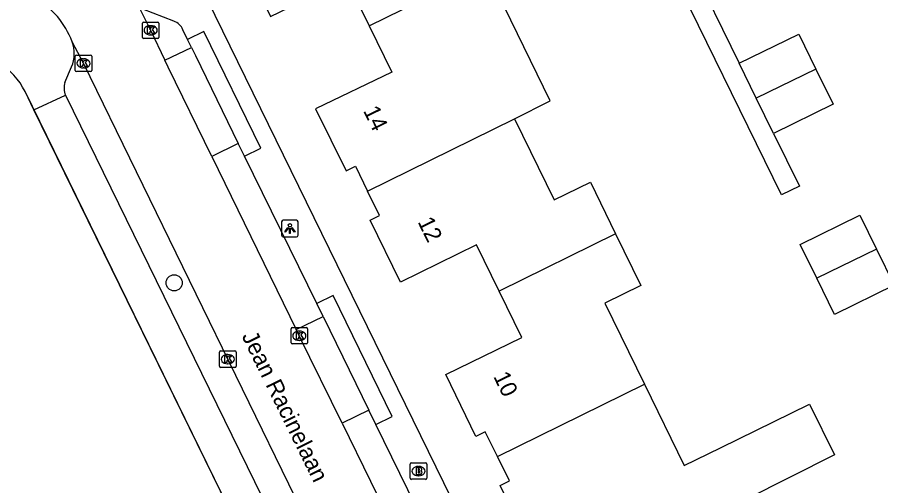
# Model space of a CAD drawing. Extents: x 160457 to 162082, y 388340 to 389736.
# Drawn here: x 160698.2 to 160750.4, y 388899 to 388927.4 of the extents above; entities that cross this region are included whole.
import ezdxf

# ---------------------------------------------------------------- set-up
doc = ezdxf.new("R2010")
doc.units = 0
for name, color, linetype in [('IMGEO_Boom', 7, 'Continuous'), ('IMGEO_Brandkraan', 7, 'Continuous'), ('IMGEO_Kolk', 7, 'Continuous'), ('IMGEO_Lichtpunt', 7, 'Continuous'), ('IMGEO_Muur', 7, 'Continuous'), ('IMGEO_Openbare_ruimte_label', 7, 'Continuous'), ('IMGEO_Pand', 7, 'Continuous'), ('IMGEO_Pand_nummerreeks', 7, 'Continuous'), ('IMGEO_Parkeervlak_open', 7, 'Continuous'), ('IMGEO_Rijbaan_lokaal_gesloten', 7, 'Continuous'), ('IMGEO_Rijbaan_lokaal_open', 7, 'Continuous'), ('IMGEO_Voetpad_open', 7, 'Continuous')]:
    doc.layers.add(name, color=color, linetype=linetype)

msp = doc.modelspace()

# ---------------------------------------------------------------- linework, layer by layer
at = {"layer": 'IMGEO_Boom'}
msp.add_circle((160707.652, 388911.311), 0.489, dxfattribs=at)
at = {"layer": 'IMGEO_Brandkraan'}
for p, q in [((160721.93, 388899.495), (160721.93, 388900.347)), ((160722.005, 388900.421), (160722.857, 388900.421)), ((160722.931, 388900.347), (160722.931, 388899.495)), ((160722.418, 388900.201), (160722.443, 388900.201)), ((160722.857, 388899.421), (160722.005, 388899.421)), ((160722.441, 388899.641), (160722.416, 388899.641))]:
    msp.add_line(p, q, dxfattribs=at)
for points in [[(160721.93, 388899.495), (160721.93, 388900.347)], [(160722.005, 388900.421), (160722.857, 388900.421)], [(160722.931, 388900.347), (160722.931, 388899.495)], [(160722.278, 388900.121), (160722.278, 388899.721), (160722.491, 388899.721)], [(160722.509, 388900.121), (160722.278, 388900.121)], [(160722.457, 388900.04), (160722.403, 388900.04), (160722.403, 388899.964)], [(160722.403, 388899.964), (160722.456, 388899.964)], [(160722.465, 388899.888), (160722.403, 388899.888), (160722.403, 388899.807)], [(160722.403, 388899.807), (160722.465, 388899.807)], [(160722.857, 388899.421), (160722.005, 388899.421)]]:
    msp.add_lwpolyline(points, dxfattribs=at)
for centre, radius, start, end in [((160722.007, 388900.345), 0.0765, 91.552, 178.448), ((160722.007, 388900.345), 0.0765, 91.552, 178.448), ((160722.855, 388900.345), 0.0765, 1.552, 88.448), ((160722.855, 388900.345), 0.0765, 1.552, 88.448), ((160722.458, 388900.002), 0.0379, 267.8285, 90.9355), ((160722.466, 388899.847), 0.0404, 269.8759, 90.5077), ((160722.497, 388899.972), 0.251, 268.6676, 293.5347), ((160722.513, 388899.976), 0.145, 59.4692, 91.5367), ((160722.538, 388900.023), 0.0922, 285.5137, 58.1501), ((160722.543, 388899.831), 0.105, 301.3115, 78.989), ((160722.007, 388899.497), 0.0765, 181.552, 268.448), ((160722.007, 388899.497), 0.0765, 181.552, 268.448), ((160722.855, 388899.497), 0.0765, 271.552, 358.448), ((160722.855, 388899.497), 0.0765, 271.552, 358.448)]:
    msp.add_arc(centre, radius, start, end, dxfattribs=at)
for centre, major_axis, ratio, start_param, end_param in [((160722.417, 388899.921), (-0.387, 0.002), 0.722429, 4.712389, 7.853982), ((160722.442, 388899.921), (-0.39, 0.002), 0.717154, 1.570796, 4.712389)]:
    msp.add_ellipse(centre, major_axis=major_axis, ratio=ratio, start_param=start_param, end_param=end_param, dxfattribs=at)
at = {"layer": 'IMGEO_Kolk'}
for p, q in [((160705.728, 388926.167), (160705.728, 388927.019)), ((160705.803, 388927.093), (160706.655, 388927.093)), ((160706.216, 388926.873), (160706.241, 388926.873)), ((160706.729, 388927.019), (160706.729, 388926.167)), ((160706.655, 388926.093), (160705.803, 388926.093)), ((160706.239, 388926.313), (160706.214, 388926.313)), ((160701.669, 388924.168), (160701.669, 388925.02)), ((160701.744, 388925.094), (160702.596, 388925.094)), ((160702.157, 388924.874), (160702.182, 388924.874)), ((160702.67, 388925.02), (160702.67, 388924.168)), ((160702.18, 388924.314), (160702.155, 388924.314)), ((160702.596, 388924.094), (160701.744, 388924.094)), ((160714.795, 388908.611), (160715.647, 388908.611)), ((160714.72, 388907.685), (160714.72, 388908.537)), ((160715.208, 388908.391), (160715.233, 388908.391)), ((160715.721, 388908.537), (160715.721, 388907.685)), ((160715.647, 388907.611), (160714.795, 388907.611)), ((160715.231, 388907.831), (160715.206, 388907.831)), ((160710.393, 388906.269), (160710.393, 388907.121)), ((160710.468, 388907.195), (160711.32, 388907.195)), ((160711.394, 388907.121), (160711.394, 388906.269)), ((160710.881, 388906.975), (160710.906, 388906.975)), ((160711.32, 388906.195), (160710.468, 388906.195)), ((160710.904, 388906.415), (160710.879, 388906.415))]:
    msp.add_line(p, q, dxfattribs=at)
for points in [[(160705.728, 388926.167), (160705.728, 388927.019)], [(160705.803, 388927.093), (160706.655, 388927.093)], [(160706.729, 388927.019), (160706.729, 388926.167)], [(160706.049, 388926.793), (160706.172, 388926.793), (160706.172, 388926.642), (160706.302, 388926.793), (160706.466, 388926.793), (160706.32, 388926.642), (160706.473, 388926.393), (160706.321, 388926.393), (160706.236, 388926.557), (160706.172, 388926.49), (160706.172, 388926.393), (160706.049, 388926.393), (160706.049, 388926.793)], [(160706.655, 388926.093), (160705.803, 388926.093)], [(160701.669, 388924.168), (160701.669, 388925.02)], [(160701.744, 388925.094), (160702.596, 388925.094)], [(160701.99, 388924.794), (160702.113, 388924.794), (160702.113, 388924.643), (160702.243, 388924.794), (160702.407, 388924.794), (160702.261, 388924.643), (160702.414, 388924.394), (160702.262, 388924.394), (160702.177, 388924.558), (160702.113, 388924.491), (160702.113, 388924.394), (160701.99, 388924.394), (160701.99, 388924.794)], [(160702.67, 388925.02), (160702.67, 388924.168)], [(160702.596, 388924.094), (160701.744, 388924.094)], [(160714.795, 388908.611), (160715.647, 388908.611)], [(160714.72, 388907.685), (160714.72, 388908.537)], [(160715.041, 388908.311), (160715.164, 388908.311), (160715.164, 388908.16), (160715.294, 388908.311), (160715.458, 388908.311), (160715.312, 388908.16), (160715.465, 388907.911), (160715.313, 388907.911), (160715.228, 388908.075), (160715.164, 388908.008), (160715.164, 388907.911), (160715.041, 388907.911), (160715.041, 388908.311)], [(160715.721, 388908.537), (160715.721, 388907.685)], [(160715.647, 388907.611), (160714.795, 388907.611)], [(160710.393, 388906.269), (160710.393, 388907.121)], [(160710.468, 388907.195), (160711.32, 388907.195)], [(160711.394, 388907.121), (160711.394, 388906.269)], [(160710.714, 388906.895), (160710.837, 388906.895), (160710.837, 388906.744), (160710.967, 388906.895), (160711.131, 388906.895), (160710.985, 388906.744), (160711.138, 388906.495), (160710.986, 388906.495), (160710.901, 388906.659), (160710.837, 388906.592), (160710.837, 388906.495), (160710.714, 388906.495), (160710.714, 388906.895)], [(160711.32, 388906.195), (160710.468, 388906.195)]]:
    msp.add_lwpolyline(points, dxfattribs=at)
for centre, start, end in [((160705.805, 388927.017), 91.552, 178.448), ((160705.805, 388927.017), 91.552, 178.448), ((160706.653, 388927.017), 1.552, 88.448), ((160706.653, 388927.017), 1.552, 88.448), ((160705.805, 388926.169), 181.552, 268.448), ((160705.805, 388926.169), 181.552, 268.448), ((160706.653, 388926.169), 271.552, 358.448), ((160706.653, 388926.169), 271.552, 358.448), ((160701.746, 388925.018), 91.552, 178.448), ((160701.746, 388925.018), 91.552, 178.448), ((160702.594, 388925.018), 1.552, 88.448), ((160702.594, 388925.018), 1.552, 88.448), ((160701.746, 388924.17), 181.552, 268.448), ((160701.746, 388924.17), 181.552, 268.448), ((160702.594, 388924.17), 271.552, 358.448), ((160702.594, 388924.17), 271.552, 358.448), ((160714.797, 388908.535), 91.552, 178.448), ((160714.797, 388908.535), 91.552, 178.448), ((160715.645, 388908.535), 1.552, 88.448), ((160715.645, 388908.535), 1.552, 88.448), ((160714.797, 388907.687), 181.552, 268.448), ((160714.797, 388907.687), 181.552, 268.448), ((160715.645, 388907.687), 271.552, 358.448), ((160715.645, 388907.687), 271.552, 358.448), ((160710.47, 388907.119), 91.552, 178.448), ((160710.47, 388907.119), 91.552, 178.448), ((160711.318, 388907.119), 1.552, 88.448), ((160711.318, 388907.119), 1.552, 88.448), ((160710.47, 388906.271), 181.552, 268.448), ((160710.47, 388906.271), 181.552, 268.448), ((160711.318, 388906.271), 271.552, 358.448), ((160711.318, 388906.271), 271.552, 358.448)]:
    msp.add_arc(centre, 0.0765, start, end, dxfattribs=at)
for centre, major_axis, ratio, start_param, end_param in [((160706.215, 388926.593), (-0.387, 0.002), 0.722429, 4.712389, 7.853982), ((160706.24, 388926.593), (-0.39, 0.002), 0.717154, 1.570796, 4.712389), ((160702.156, 388924.594), (-0.387, 0.002), 0.722429, 4.712389, 7.853982), ((160702.181, 388924.594), (-0.39, 0.002), 0.717154, 1.570796, 4.712389), ((160715.207, 388908.111), (-0.387, 0.002), 0.722429, 4.712389, 7.853982), ((160715.232, 388908.111), (-0.39, 0.002), 0.717154, 1.570796, 4.712389), ((160710.88, 388906.695), (-0.387, 0.002), 0.722429, 4.712389, 7.853982), ((160710.905, 388906.695), (-0.39, 0.002), 0.717154, 1.570796, 4.712389)]:
    msp.add_ellipse(centre, major_axis=major_axis, ratio=ratio, start_param=start_param, end_param=end_param, dxfattribs=at)
at = {"layer": 'IMGEO_Lichtpunt'}
for p, q in [((160714.15, 388914.999), (160714.15, 388914.192)), ((160714.15, 388914.999), (160714.15, 388914.192)), ((160715.052, 388915.094), (160714.244, 388915.094)), ((160715.052, 388915.094), (160714.244, 388915.094)), ((160715.146, 388914.192), (160715.146, 388914.999)), ((160715.146, 388914.192), (160715.146, 388914.999)), ((160714.244, 388914.098), (160715.052, 388914.098)), ((160714.244, 388914.098), (160715.052, 388914.098))]:
    msp.add_line(p, q, dxfattribs=at)
for points in [[(160714.524, 388914.663), (160714.563, 388914.635), (160714.375, 388914.373), (160714.337, 388914.4), (160714.524, 388914.663)], [(160714.626, 388914.615), (160714.673, 388914.615), (160714.673, 388914.293), (160714.626, 388914.293), (160714.626, 388914.615)], [(160714.736, 388914.635), (160714.774, 388914.662), (160714.961, 388914.4), (160714.922, 388914.372), (160714.736, 388914.635)]]:
    msp.add_lwpolyline(points, dxfattribs=at)
msp.add_circle((160714.649, 388914.797), 0.0994, dxfattribs=at)
for centre, start, end in [((160714.244, 388914.999), 90, 180), ((160714.244, 388914.999), 90, 180), ((160715.052, 388914.999), 0, 90), ((160715.052, 388914.999), 0, 90), ((160714.244, 388914.192), 180, 270), ((160714.244, 388914.192), 180, 270), ((160715.052, 388914.192), 270, 0), ((160715.052, 388914.192), 270, 360)]:
    msp.add_arc(centre, 0.0946, start, end, dxfattribs=at)
at = {"layer": 'IMGEO_Muur'}
msp.add_lwpolyline([(160711.402, 388896.761), (160698.632, 388922.881)], dxfattribs=at)
msp.add_arc((160694.823, 388921.023), 4.238, 26.0033, 154.6119, dxfattribs=at)
at = {"layer": 'IMGEO_Pand'}
for points in [[(160711.473, 388932.933), (160712.196, 388931.461), (160711.631, 388931.184), (160713.469, 388927.434), (160718.071, 388929.671), (160719.442, 388926.87)], [(160719.442, 388926.87), (160726.489, 388930.328)], [(160728.231, 388921.239), (160730.401, 388922.33), (160728.012, 388927.214), (160726.489, 388930.328)], [(160719.442, 388926.87), (160720.813, 388924.069), (160716.205, 388921.838), (160718.045, 388918.085), (160718.61, 388918.362), (160719.343, 388916.864)], [(160741.823, 388924.598), (160745.425, 388926.361), (160746.459, 388924.249)], [(160742.852, 388922.496), (160741.823, 388924.598)], [(160746.459, 388924.249), (160742.852, 388922.496)], [(160746.459, 388924.249), (160747.501, 388922.119), (160743.899, 388920.357)], [(160743.899, 388920.357), (160742.852, 388922.496)], [(160719.343, 388916.864), (160728.231, 388921.239)], [(160728.231, 388921.239), (160730.632, 388916.33), (160732.822, 388917.401), (160734.349, 388914.278)], [(160727.308, 388910.801), (160725.933, 388913.611), (160721.342, 388911.358), (160719.499, 388915.112), (160720.065, 388915.39), (160719.343, 388916.864)], [(160746.518, 388911.592), (160745.516, 388913.639), (160749.117, 388915.402), (160750.127, 388913.34)], [(160734.349, 388914.278), (160727.308, 388910.801)], [(160734.349, 388914.278), (160735.876, 388911.155), (160733.695, 388910.089), (160736.1, 388905.172)], [(160750.127, 388913.34), (160746.518, 388911.592)], [(160750.127, 388913.34), (160751.193, 388911.163), (160747.591, 388909.4), (160746.518, 388911.592)], [(160727.205, 388900.793), (160726.468, 388902.294), (160725.902, 388902.018), (160724.078, 388905.763), (160728.679, 388908.001), (160727.308, 388910.801)], [(160727.205, 388900.793), (160736.1, 388905.172)], [(160736.1, 388905.172), (160738.505, 388900.254), (160740.694, 388901.325), (160746.084, 388903.962), (160747.582, 388900.899), (160742.221, 388898.202), (160742.02, 388898.103)], [(160735.174, 388894.733), (160733.799, 388897.543), (160729.198, 388895.296), (160727.362, 388899.044), (160727.928, 388899.321), (160727.205, 388900.793)]]:
    msp.add_lwpolyline(points, dxfattribs=at)
at = {"layer": 'IMGEO_Parkeervlak_open'}
for points in [[(160707.087, 388924.788), (160708.698, 388925.555)], [(160711.531, 388919.737), (160709.928, 388918.955)], [(160715.034, 388908.492), (160716.656, 388909.283)], [(160719.419, 388903.605), (160717.809, 388902.817)]]:
    msp.add_lwpolyline(points, dxfattribs=at)
at = {"layer": 'IMGEO_Rijbaan_lokaal_gesloten'}
for points in [[(160705.518, 388928.008), (160706.228, 388926.593), (160707.087, 388924.788)], [(160714.987, 388898.304), (160702.171, 388924.594), (160701.48, 388925.903)], [(160709.928, 388918.955), (160707.289, 388924.364), (160707.087, 388924.788)], [(160709.928, 388918.955), (160715.034, 388908.492)], [(160717.809, 388902.817), (160715.22, 388908.111), (160715.034, 388908.492)], [(160717.809, 388902.817), (160722.954, 388892.3)]]:
    msp.add_lwpolyline(points, dxfattribs=at)
msp.add_arc((160696.15, 388923.847), 5.713, 21.0914, 38.8024, dxfattribs=at)
at = {"layer": 'IMGEO_Rijbaan_lokaal_open'}
msp.add_arc((160694.928, 388922.191), 7.721, 42.7017, 151.2116, dxfattribs=at)
at = {"layer": 'IMGEO_Voetpad_open'}
for points in [[(160743.899, 388920.357), (160745.465, 388917.158), (160744.386, 388916.63), (160730.313, 388945.38), (160730.986, 388947.021), (160732.891, 388947.051), (160731.827, 388944.767), (160736.003, 388936.427)], [(160746.543, 388853.042), (160702.295, 388943.534)], [(160738.811, 388930.755), (160741.823, 388924.598)], [(160707.629, 388927.15), (160705.759, 388927.875), (160705.639, 388927.943), (160705.518, 388928.008)], [(160708.463, 388926.045), (160708.184, 388926.626)], [(160711.899, 388918.983), (160712.888, 388919.464), (160709.452, 388926.526), (160708.463, 388926.045)], [(160708.698, 388925.555), (160708.463, 388926.045)], [(160708.698, 388925.555), (160708.934, 388925.065), (160711.531, 388919.737)], [(160701.049, 388923.442), (160701.451, 388924.376)], [(160699.17, 388921.78), (160698.632, 388922.881)], [(160699.17, 388921.78), (160701.075, 388922.662)], [(160701.075, 388922.662), (160712.966, 388898.338)], [(160741.386, 388835.41), (160711.402, 388896.761), (160699.17, 388921.78)], [(160711.899, 388918.983), (160711.531, 388919.737)], [(160716.276, 388910.063), (160711.899, 388918.983)], [(160719.841, 388902.738), (160720.83, 388903.219), (160717.265, 388910.544), (160716.276, 388910.063)], [(160716.656, 388909.283), (160716.276, 388910.063)], [(160716.656, 388909.283), (160719.419, 388903.605)], [(160719.841, 388902.738), (160719.419, 388903.605)], [(160724.214, 388893.81), (160719.841, 388902.738)]]:
    msp.add_lwpolyline(points, dxfattribs=at)
for centre, radius, start, end in [((160707.269, 388926.213), 1.004, 24.3093, 68.9821), ((160699.563, 388925.176), 2.05, 337.0444, 20.7796), ((160694.823, 388921.023), 4.238, 26.0033, 154.6119), ((160702.164, 388923.089), 1.169, 162.4154, 201.4029)]:
    msp.add_arc(centre, radius, start, end, dxfattribs=at)

# ---------------------------------------------------------------- texts
at = {"layer": 'IMGEO_Openbare_ruimte_label'}
msp.add_text('Jean Racinelaan', height=1, rotation=296.2319, dxfattribs=at).set_placement((160711.716, 388908.09))
at = {"layer": 'IMGEO_Pand_nummerreeks'}
for s, rotation, p in [('14', 296.1152, (160719.064, 388921.731)), ('12', 296.1484, (160722.358, 388915.008)), ('10', 295.9684, (160726.935, 388905.652))]:
    msp.add_text(s, height=1, rotation=rotation, dxfattribs=at).set_placement(p)

doc.saveas('drawing.dxf')
